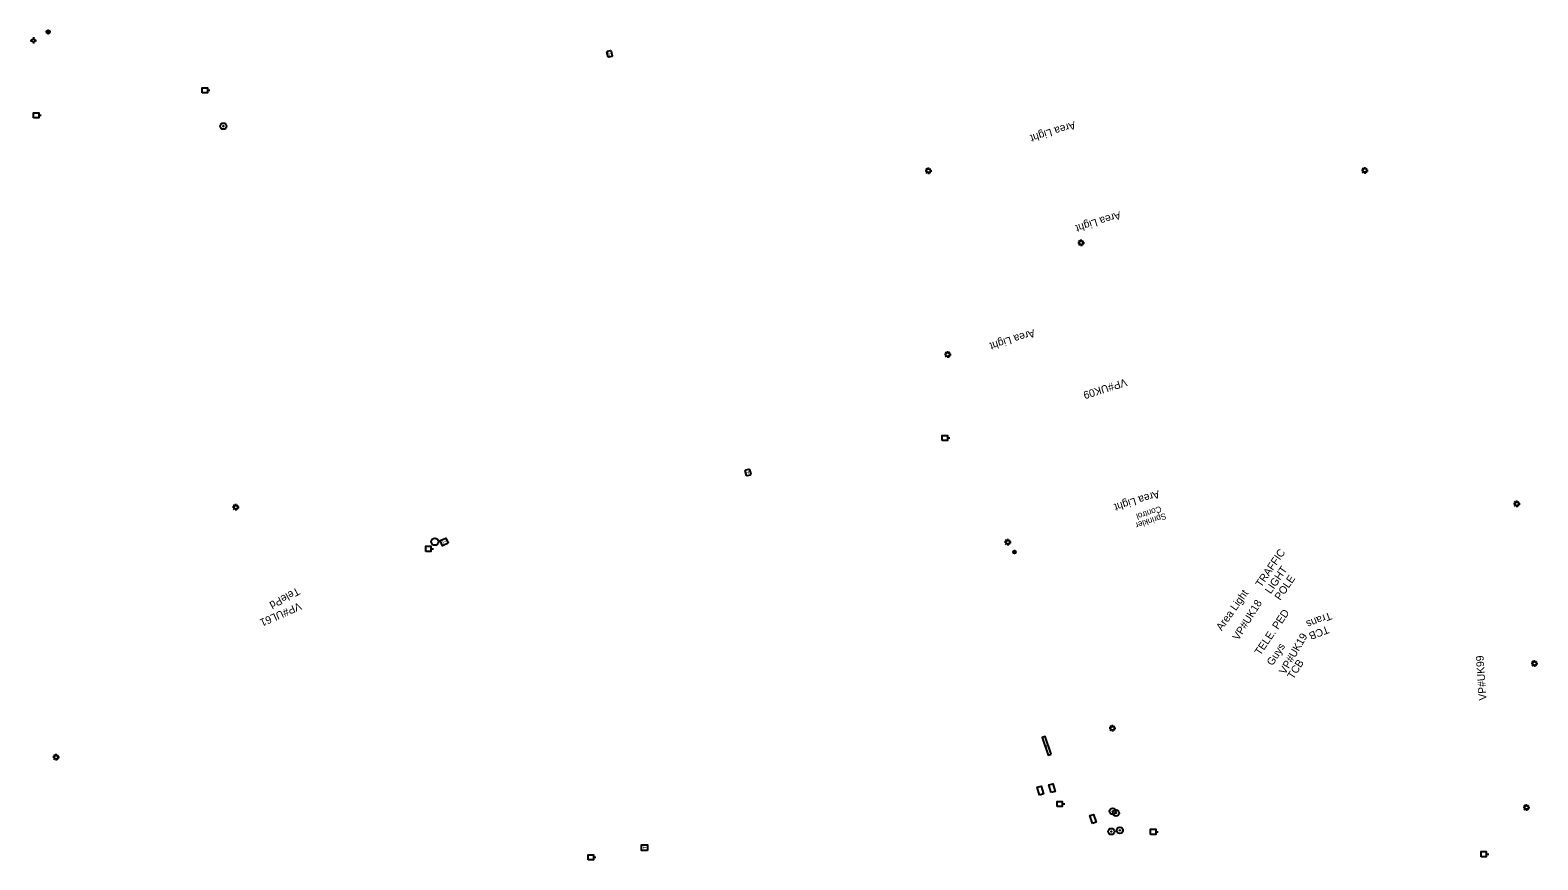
# Model space of a CAD drawing. Extents: x 3872070 to 3879223, y 293944 to 310567.
# Drawn here: x 3874024 to 3874614, y 307660 to 307985 of the extents above; entities that cross this region are included whole.
import ezdxf

# ---------------------------------------------------------------- set-up
doc = ezdxf.new("R2010")
doc.units = 0
for name, color, linetype in [('Level 11', 7, 'Continuous'), ('Level 34', 7, 'Continuous'), ('Level 35', 7, 'Continuous'), ('Level 37', 7, 'Continuous'), ('Level 39', 7, 'Continuous'), ('Level 4', 7, 'Continuous'), ('Level 5', 7, 'Continuous'), ('Level 7', 7, 'Continuous'), ('Level 9', 7, 'Continuous')]:
    doc.layers.add(name, color=color, linetype=linetype)

msp = doc.modelspace()

# ---------------------------------------------------------------- linework, layer by layer
at = {"layer": 'Level 11'}
msp.add_circle((3874182.57, 307784.73), 1.41, dxfattribs=at)
at = {"layer": 'Level 4'}
for p, q in [((3874093.66, 307961.16), (3874094.66, 307961.16)), ((3874027.77, 307951.38), (3874028.77, 307951.38)), ((3874374.77, 307929.72), (3874374.2, 307929.72)), ((3874374.98, 307930.23), (3874374.58, 307930.64)), ((3874374.58, 307928.8), (3874374.98, 307929.21)), ((3874375.5, 307930.45), (3874375.5, 307931.02)), ((3874375.5, 307929), (3874375.5, 307928.42)), ((3874376.01, 307930.23), (3874376.42, 307930.64)), ((3874376.42, 307928.8), (3874376.01, 307929.21)), ((3874376.22, 307929.72), (3874376.8, 307929.72)), ((3874545.34, 307929.85), (3874544.77, 307929.85)), ((3874545.56, 307930.36), (3874545.15, 307930.77)), ((3874545.15, 307928.93), (3874545.56, 307929.34)), ((3874546.07, 307930.57), (3874546.07, 307931.15)), ((3874546.07, 307929.12), (3874546.07, 307928.55)), ((3874546.58, 307930.36), (3874546.99, 307930.77)), ((3874546.99, 307928.93), (3874546.58, 307929.34)), ((3874546.79, 307929.85), (3874547.37, 307929.85)), ((3874434.49, 307901.5), (3874433.91, 307901.5)), ((3874434.7, 307902.02), (3874434.29, 307902.42)), ((3874434.29, 307900.58), (3874434.7, 307900.99)), ((3874435.21, 307902.23), (3874435.21, 307902.8)), ((3874435.21, 307900.78), (3874435.21, 307900.2)), ((3874435.73, 307902.02), (3874436.13, 307902.42)), ((3874436.13, 307900.58), (3874435.73, 307900.99)), ((3874435.94, 307901.5), (3874436.51, 307901.5)), ((3874382.33, 307857.89), (3874381.75, 307857.89)), ((3874382.54, 307858.4), (3874382.13, 307858.81)), ((3874383.05, 307858.61), (3874383.05, 307859.19)), ((3874383.56, 307858.4), (3874383.97, 307858.81)), ((3874383.78, 307857.89), (3874384.35, 307857.89)), ((3874382.13, 307856.97), (3874382.54, 307857.37)), ((3874383.05, 307857.16), (3874383.05, 307856.59)), ((3874383.97, 307856.97), (3874383.56, 307857.37)), ((3874382.94, 307825.29), (3874383.94, 307825.29)), ((3874104.33, 307798.7), (3874103.92, 307799.1)), ((3874104.84, 307798.91), (3874104.84, 307799.48)), ((3874105.35, 307798.7), (3874105.76, 307799.1)), ((3874604.81, 307799.51), (3874604.24, 307799.51)), ((3874605.03, 307800.02), (3874604.62, 307800.43)), ((3874604.62, 307798.59), (3874605.03, 307799)), ((3874605.54, 307800.23), (3874605.54, 307800.81)), ((3874605.54, 307798.79), (3874605.54, 307798.21)), ((3874606.05, 307800.02), (3874606.46, 307800.43)), ((3874606.46, 307798.59), (3874606.05, 307799)), ((3874606.26, 307799.51), (3874606.84, 307799.51)), ((3874104.12, 307798.18), (3874103.54, 307798.18)), ((3874103.92, 307797.27), (3874104.33, 307797.67)), ((3874104.84, 307797.46), (3874104.84, 307796.89)), ((3874105.76, 307797.27), (3874105.35, 307797.67)), ((3874105.56, 307798.18), (3874106.14, 307798.18)), ((3874181.05, 307781.96), (3874182.05, 307781.96)), ((3874405.84, 307784.52), (3874405.26, 307784.52)), ((3874406.05, 307785.04), (3874405.64, 307785.44)), ((3874405.64, 307783.6), (3874406.05, 307784.01)), ((3874406.56, 307785.25), (3874406.56, 307785.82)), ((3874406.56, 307783.8), (3874406.56, 307783.22)), ((3874407.08, 307785.04), (3874407.48, 307785.44)), ((3874407.48, 307783.6), (3874407.08, 307784.01)), ((3874407.29, 307784.52), (3874407.86, 307784.52)), ((3874611.7, 307737.13), (3874611.13, 307737.13)), ((3874611.92, 307737.65), (3874611.51, 307738.05)), ((3874611.51, 307736.21), (3874611.92, 307736.62)), ((3874612.43, 307737.86), (3874612.43, 307738.43)), ((3874612.43, 307736.41), (3874612.43, 307735.83)), ((3874612.94, 307737.65), (3874613.35, 307738.05)), ((3874613.35, 307736.21), (3874612.94, 307736.62)), ((3874613.15, 307737.13), (3874613.73, 307737.13)), ((3874446.71, 307711.8), (3874446.14, 307711.8)), ((3874446.92, 307712.32), (3874446.52, 307712.72)), ((3874446.52, 307710.89), (3874446.92, 307711.29)), ((3874447.44, 307712.53), (3874447.44, 307713.1)), ((3874447.44, 307711.08), (3874447.44, 307710.51)), ((3874447.95, 307712.32), (3874448.36, 307712.72)), ((3874448.36, 307710.89), (3874447.95, 307711.29)), ((3874448.16, 307711.8), (3874448.74, 307711.8)), ((3874033.81, 307700.51), (3874033.23, 307700.51)), ((3874034.02, 307701.03), (3874033.61, 307701.43)), ((3874033.61, 307699.59), (3874034.02, 307700)), ((3874034.53, 307701.24), (3874034.53, 307701.81)), ((3874034.53, 307699.79), (3874034.53, 307699.21)), ((3874035.04, 307701.03), (3874035.45, 307701.43)), ((3874035.45, 307699.59), (3874035.04, 307700)), ((3874035.26, 307700.51), (3874035.83, 307700.51)), ((3874427.85, 307682.25), (3874428.85, 307682.25)), ((3874608.6, 307680.87), (3874608.03, 307680.87)), ((3874608.82, 307681.38), (3874608.41, 307681.79)), ((3874609.33, 307681.59), (3874609.33, 307682.17)), ((3874609.84, 307681.38), (3874610.25, 307681.79)), ((3874610.06, 307680.87), (3874610.63, 307680.87)), ((3874608.41, 307679.95), (3874608.82, 307680.35)), ((3874609.33, 307680.14), (3874609.33, 307679.57)), ((3874610.25, 307679.95), (3874609.84, 307680.35)), ((3874464.35, 307671.35), (3874465.35, 307671.35)), ((3874244.55, 307661.4), (3874245.55, 307661.4)), ((3874593.59, 307662.6), (3874594.59, 307662.6))]:
    msp.add_line(p, q, dxfattribs=at)
for points in [[(3874091.66, 307960.16), (3874091.66, 307962.16), (3874093.66, 307962.16), (3874093.66, 307960.16)], [(3874025.77, 307950.38), (3874025.77, 307952.38), (3874027.77, 307952.38), (3874027.77, 307950.38)], [(3874380.94, 307824.29), (3874380.94, 307826.29), (3874382.94, 307826.29), (3874382.94, 307824.29)], [(3874179.05, 307780.96), (3874179.05, 307782.96), (3874181.05, 307782.96), (3874181.05, 307780.96)], [(3874425.85, 307681.25), (3874425.85, 307683.25), (3874427.85, 307683.25), (3874427.85, 307681.25)], [(3874462.35, 307670.35), (3874462.35, 307672.35), (3874464.35, 307672.35), (3874464.35, 307670.35)], [(3874591.59, 307661.6), (3874591.59, 307663.6), (3874593.59, 307663.6), (3874593.59, 307661.6)], [(3874242.55, 307660.4), (3874242.55, 307662.4), (3874244.55, 307662.4), (3874244.55, 307660.4)]]:
    msp.add_lwpolyline(points, close=True, dxfattribs=at)
for centre, radius in [((3874099.9, 307947.13), 1.22), ((3874099.9, 307947.13), 0.0992), ((3874099.9, 307947.13), 0.0483), ((3874375.5, 307929.72), 0.725), ((3874546.07, 307929.85), 0.725), ((3874435.21, 307901.5), 0.725), ((3874383.05, 307857.89), 0.725), ((3874104.84, 307798.18), 0.725), ((3874605.54, 307799.51), 0.725), ((3874406.56, 307784.52), 0.725), ((3874612.43, 307737.13), 0.725), ((3874447.44, 307711.8), 0.725), ((3874034.53, 307700.51), 0.725), ((3874609.33, 307680.87), 0.725), ((3874447.58, 307679.36), 1.22), ((3874447.58, 307679.36), 0.0992), ((3874447.58, 307679.36), 0.0483), ((3874448.84, 307678.7), 1.22), ((3874448.84, 307678.7), 0.0992), ((3874448.84, 307678.7), 0.0483), ((3874447.01, 307671.46), 1.22), ((3874447.01, 307671.46), 0.0992), ((3874447.01, 307671.46), 0.0483), ((3874450.34, 307671.93), 1.22), ((3874450.34, 307671.93), 0.0992), ((3874450.34, 307671.93), 0.0483)]:
    msp.add_circle(centre, radius, dxfattribs=at)
at = {"layer": 'Level 5'}
for p, q in [((3874025.65, 307981.87), (3874025.65, 307981.23)), ((3874030.59, 307983.95), (3874030.95, 307983.95)), ((3874030.95, 307983.95), (3874031.95, 307983.95)), ((3874031.95, 307983.95), (3874032.31, 307983.95)), ((3874024.4, 307980.62), (3874025.02, 307980.62)), ((3874025.65, 307979.99), (3874025.65, 307979.37)), ((3874026.27, 307980.62), (3874026.9, 307980.62)), ((3874409.17, 307781.39), (3874409.17, 307780.67)), ((3874409.17, 307781.08), (3874409.17, 307780.25)), ((3874409.17, 307780.67), (3874409.17, 307779.95))]:
    msp.add_line(p, q, dxfattribs=at)
for centre, radius in [((3874031.45, 307983.95), 0.7), ((3874025.65, 307980.62), 0.625), ((3874409.17, 307780.67), 0.583)]:
    msp.add_circle(centre, radius, dxfattribs=at)
for centre, radius, start, end in [((3874031.45, 307983.95), 0.5, 0, 180), ((3874409.17, 307780.67), 0.417, 270, 90)]:
    msp.add_arc(centre, radius, start, end, dxfattribs=at)
at = {"layer": 'Level 7'}
for points in [[(3874187.81, 307784.17), (3874185.62, 307783.17), (3874184.71, 307785.16), (3874186.9, 307786.16)], [(3874265.75, 307664.05), (3874263.35, 307664.05), (3874263.35, 307666.24), (3874265.75, 307666.24)]]:
    msp.add_lwpolyline(points, close=True, dxfattribs=at)
msp.add_lwpolyline([(3874423.45, 307701.71), (3874421.1, 307708.57), (3874419.92, 307708.16), (3874422.28, 307701.3), (3874423.45, 307701.71)], dxfattribs=at)
at = {"layer": 'Level 9'}
for points in [[(3874250.28, 307974.22), (3874249.83, 307976.07), (3874250.02, 307976.38), (3874251.21, 307976.66), (3874251.51, 307976.47), (3874251.96, 307974.62), (3874251.77, 307974.32), (3874250.58, 307974.03)], [(3874305.6, 307812.91), (3874306.05, 307811.06), (3874305.86, 307810.76), (3874304.67, 307810.47), (3874304.37, 307810.66), (3874303.92, 307812.51), (3874304.11, 307812.81), (3874305.3, 307813.1)], [(3874418.94, 307685.69), (3874418.04, 307688.76), (3874419.54, 307689.2), (3874420.45, 307686.14)], [(3874423.52, 307686.65), (3874422.62, 307689.71), (3874424.13, 307690.16), (3874425.03, 307687.1)]]:
    msp.add_lwpolyline(points, close=True, dxfattribs=at)
msp.add_lwpolyline([(3874439.61, 307674.64), (3874438.57, 307677.68), (3874439.99, 307678.17), (3874441.04, 307675.13), (3874439.61, 307674.64)], dxfattribs=at)

# ---------------------------------------------------------------- texts
at = {"layer": 'Level 34'}
for s, rotation, p in [('Area Light', 197.24972, (3874432.52, 307949.05)), ('Area Light', 197.24972, (3874450.23, 307913.84)), ('Area Light', 197.24972, (3874416.65, 307867.8)), ('VP#UK09', 197.45811, (3874452.58, 307848.55)), ('Area Light', 197.24972, (3874465.37, 307804.85)), ('Area Light', 54.62918, (3874490.13, 307749.71)), ('VP#UL61', 203.69967, (3874129.62, 307761.11)), ('VP#UK18', 58.04935, (3874496.72, 307745.93)), ('Trans', 201.13993, (3874532.43, 307757.32)), ('VP#UK19', 59.94485, (3874514.99, 307732.62)), ('Guys', 57.16409, (3874510.02, 307736.02)), ('VP#UK99', 94.00234, (3874593.69, 307722.77))]:
    msp.add_text(s, height=3, rotation=rotation, dxfattribs=at).set_placement(p)
at = {"layer": 'Level 35'}
for s, p in [(' Control', (3874467, 307799.01)), ('Sprinkler', (3874468, 307795.99))]:
    msp.add_text(s, height=2.362, rotation=198.44534, dxfattribs=at).set_placement(p)
at = {"layer": 'Level 37'}
for s, rotation, p in [('TelePd', 208.28328, (3874128.81, 307766.98)), ('TELE. PED', 55.84342, (3874505.24, 307740.06))]:
    msp.add_text(s, height=3, rotation=rotation, dxfattribs=at).set_placement(p)
at = {"layer": 'Level 39'}
for s, rotation, p in [('TRAFFIC', 55.50967, (3874505.59, 307766.66)), ('LIGHT', 55.50967, (3874509.3, 307764.11)), ('POLE', 55.50967, (3874513.01, 307761.57)), ('TCB', 200.82675, (3874531.4, 307751.94)), ('TCB', 57.48455, (3874518.1, 307730.75))]:
    msp.add_text(s, height=3, rotation=rotation, dxfattribs=at).set_placement(p)
at = {"layer": 'Level 7'}
for height, rotation, p in [(1.41, 114.54311, (3874187.18, 307784.47)), (1.17, 17.70308, (3874421.43, 307703.97)), (1.41, 90, (3874265.31, 307664.58))]:
    msp.add_text('T', height=height, rotation=rotation, dxfattribs=at).set_placement(p)
at = {"layer": 'Level 9'}
for rotation, p in [(13.38214, (3874250.6, 307974.55)), (193.50622, (3874305.27, 307812.58))]:
    msp.add_text('H', height=1.41, rotation=rotation, dxfattribs=at).set_placement(p)

doc.saveas('drawing.dxf')
